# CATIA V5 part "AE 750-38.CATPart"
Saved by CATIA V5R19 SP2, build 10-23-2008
Part number: AE 750-38
Bounding box of the stored display mesh (mm): x -24.865 to 24.865, y -24.997 to 24.997, z 0 to 126
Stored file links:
  C:\Users\Bora\Desktop\3D Katı model\AE serisi\AE 750\AE 750-38.CATPart
  C:\Program Files\Dassault Systemes\B19\intel_a\reffiles\standard\MetricThickPitch.txt
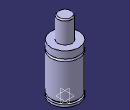
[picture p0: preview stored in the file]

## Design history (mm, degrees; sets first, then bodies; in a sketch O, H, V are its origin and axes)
Body1 (main body)
  Sketch1 on yz-plane, origin (0, 0, 0), H (0, 1, 0), V (0, 0, 1)
    point P1 (25, 70.5)
    point P8 (25, 74.5)
    point P9 (12.5, 124)
    point P11 (12.5, 124)
    point P13 (25, 74.5)
    point P14 (25, 70.5)
    line L1 (25, 70.5) -> (25, 8)
    line L2 (25, 4) -> (25, 0)
    line L3 (21.5, 8) -> (21.5, 4)
    line L4 (25, 87) -> (25, 74.5)
    line L5 (12.5, 124) -> (12.5, 87)
    arc A1 centre (10.5, 124) radius 2 from (12.5, 124) to (10.5, 126) ccw
    arc A2 centre (25, 72.5) radius 2 from (25, 74.5) to (25, 70.5) ccw
    line L6 (10.5, 126) -> (0, 126)
    point P15 (0, 126)
    line L7 (12.5, 87) -> (25, 87)
    line L8 (0, 0) -> (25, 0)
    line L9 (21.5, 8) -> (25, 8)
    line L10 (21.5, 4) -> (25, 4)
    tangency: L6 A1
    coincidence: P15 V, P1 P14, P8 P13, P9 P11
    horizontal: L7 H, L8 H, L9 H, L10 H
  Shaft1: profile Sketch1, axis Sketch1.V, angle 360
  Sketch2 on face of Shaft1 from Sketch1.L8, origin (0, 0, 0), H (1, 0, 0), V (0, -1, 0)
    point P1 (10, 0)
    distance P1 V = 10
  Hole1: placed by Sketch2, at (10, 0, 0) direction (0, 0, 1), diameter 6.647, depth 13, threaded "M8", thread diameter 8, thread depth 13, pitch 1.25
  CircPattern1: of Hole1, instances 2, angular step 180, axis from xy-plane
